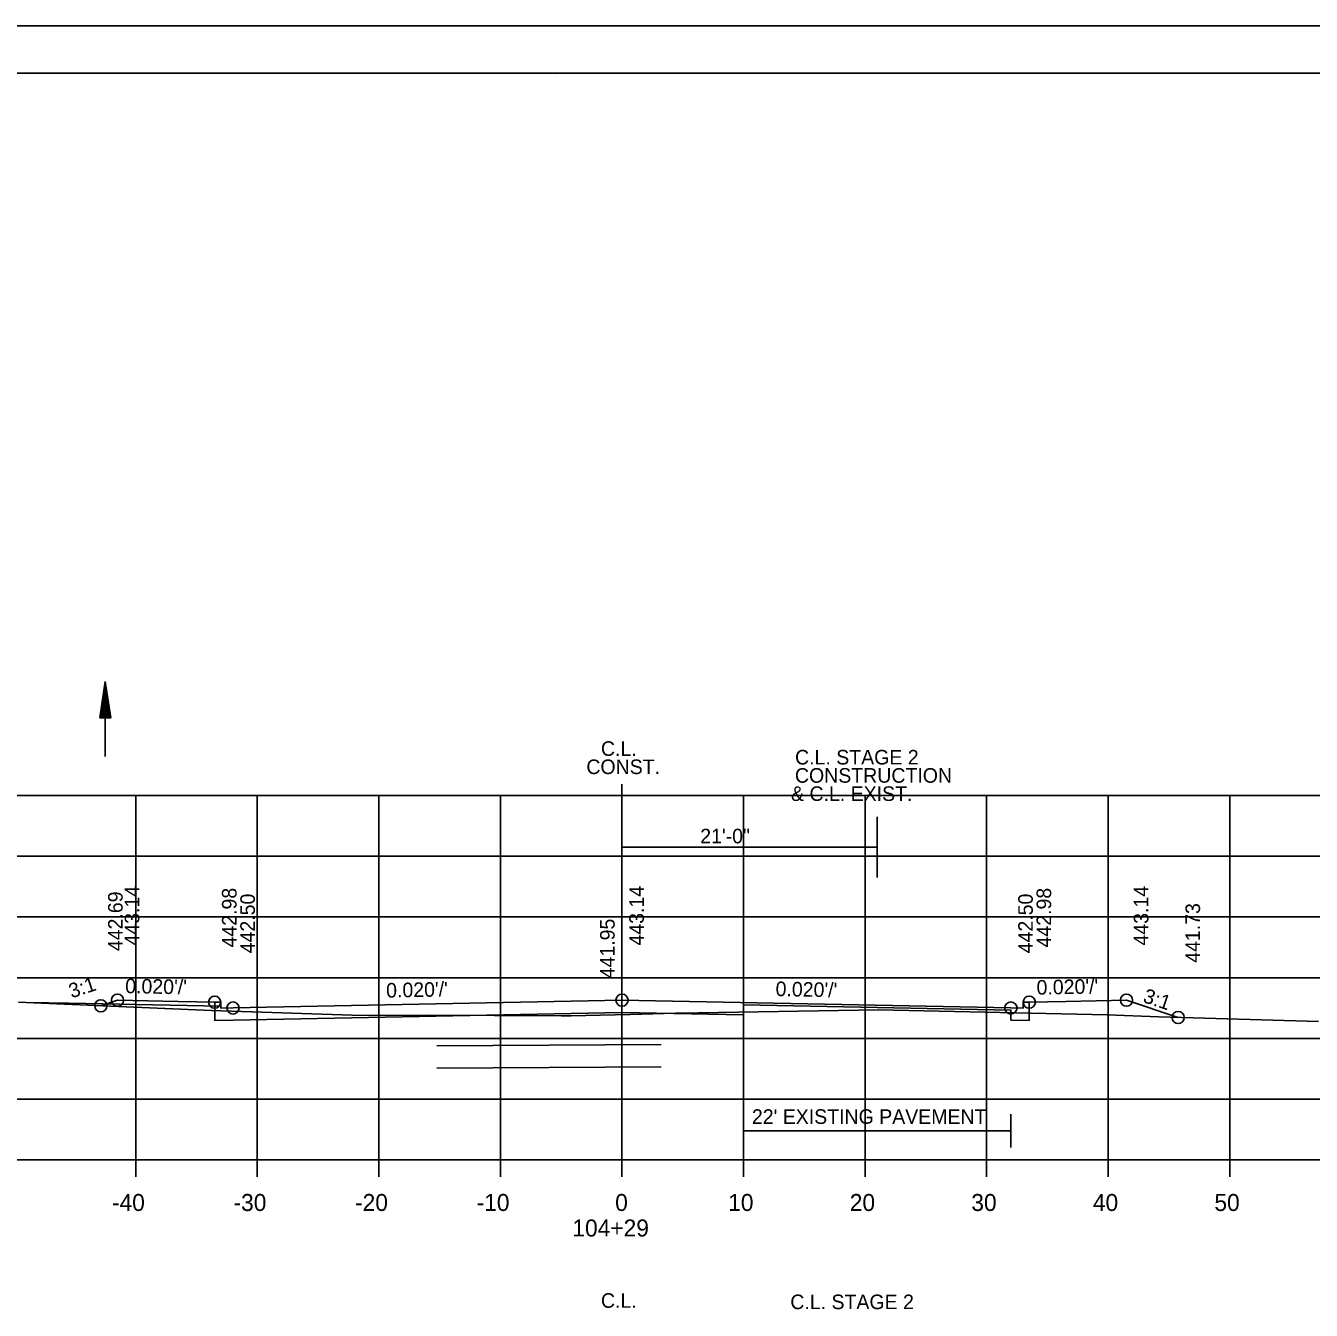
# Model space of a CAD drawing. Extents: x 1538688 to 1540766, y 656250 to 671912.
# Drawn here: x 1538809.1 to 1538914.9, y 657085.5 to 657191.2 of the extents above; entities that cross this region are included whole.
import ezdxf

# ---------------------------------------------------------------- set-up
doc = ezdxf.new("R2010")
doc.units = 0
for name, color, linetype in [('15', 7, 'Continuous'), ('16', 7, 'Continuous'), ('18', 7, 'Continuous'), ('20', 7, 'Continuous'), ('22', 7, 'Continuous'), ('26', 7, 'Continuous'), ('39', 7, 'Continuous'), ('41', 7, 'Continuous'), ('42', 7, 'Continuous'), ('7', 7, 'Continuous'), ('Borings', 7, 'Continuous'), ('Default', 7, 'Continuous'), ('Horizontal Alignment', 7, 'Continuous'), ('RipRap', 7, 'Continuous'), ('Wall Heights', 7, 'Continuous')]:
    doc.layers.add(name, color=color, linetype=linetype)

msp = doc.modelspace()

# ---------------------------------------------------------------- linework, layer by layer
at = {"layer": '15'}
for p, q in [((1538815.22, 657134.28), (1538815.67, 657137.28)), ((1538816.12, 657134.28), (1538815.67, 657137.28)), ((1538815.3, 657134.28), (1538815.67, 657136.78)), ((1538815.38, 657134.28), (1538815.67, 657136.26)), ((1538816.05, 657134.28), (1538815.67, 657136.78)), ((1538815.97, 657134.28), (1538815.67, 657136.26)), ((1538815.45, 657134.28), (1538815.67, 657135.76)), ((1538815.53, 657134.28), (1538815.67, 657135.25)), ((1538815.6, 657134.28), (1538815.67, 657134.75)), ((1538815.9, 657134.28), (1538815.67, 657135.76)), ((1538815.82, 657134.28), (1538815.67, 657135.25)), ((1538815.74, 657134.28), (1538815.67, 657134.75)), ((1538815.22, 657134.28), (1538816.12, 657134.28))]:
    msp.add_line(p, q, dxfattribs=at)
at = {"layer": '16'}
for p, q in [((1538809.4, 657110.85), (1538812.68, 657110.8)), ((1538812.68, 657110.8), (1538825.18, 657110.55))]:
    msp.add_line(p, q, dxfattribs=at)
at = {"layer": '18'}
msp.add_lwpolyline([(1538808.52, 657110.89), (1538817.4, 657110.49), (1538824.4, 657110.2), (1538836.81, 657109.79), (1538842.19, 657109.8), (1538853.2, 657109.75), (1538853.92, 657109.75), (1538853.99, 657109.75), (1538858.83, 657109.86), (1538858.85, 657109.86), (1538858.86, 657109.86), (1538862.58, 657109.97), (1538862.83, 657109.97), (1538879.29, 657110.26), (1538880.52, 657110.23), (1538898.09, 657109.84), (1538902.34, 657109.67), (1538915.48, 657109.29)], dxfattribs=at)
at = {"layer": '20'}
msp.add_lwpolyline([(1538815.3, 657110.58), (1538816.67, 657111.04), (1538821.67, 657110.94), (1538824.67, 657110.88), (1538825.17, 657110.88), (1538825.18, 657110.38), (1538826.18, 657110.4), (1538858.18, 657111.04), (1538890.18, 657110.4), (1538891.18, 657110.38), (1538891.19, 657110.88), (1538891.69, 657110.88), (1538894.69, 657110.94), (1538899.69, 657111.04), (1538903.94, 657109.62)], dxfattribs=at)
at = {"layer": '22'}
for p, q in [((1538718.18, 657127.89), (1538998.18, 657127.89)), ((1538818.18, 657097.89), (1538818.18, 657127.89)), ((1538828.18, 657097.89), (1538828.18, 657127.89)), ((1538838.18, 657097.89), (1538838.18, 657127.89)), ((1538848.18, 657097.89), (1538848.18, 657127.89)), ((1538858.18, 657097.89), (1538858.18, 657127.89)), ((1538868.18, 657097.89), (1538868.18, 657127.89)), ((1538878.18, 657097.89), (1538878.18, 657127.89)), ((1538888.18, 657097.89), (1538888.18, 657127.89)), ((1538898.18, 657097.89), (1538898.18, 657127.89)), ((1538908.18, 657097.89), (1538908.18, 657127.89)), ((1538718.18, 657122.89), (1538998.18, 657122.89)), ((1538718.18, 657117.89), (1538998.18, 657117.89)), ((1538718.18, 657112.89), (1538998.18, 657112.89)), ((1538718.18, 657107.89), (1538998.18, 657107.89)), ((1538718.18, 657102.89), (1538998.18, 657102.89)), ((1538718.18, 657097.89), (1538998.18, 657097.89))]:
    msp.add_line(p, q, dxfattribs=at)
at = {"layer": '26'}
for p, q in [((1538687.78, 657191.25), (1539021.11, 657191.25)), ((1538861.4, 657107.38), (1538842.96, 657107.27)), ((1538861.4, 657105.55), (1538842.96, 657105.44))]:
    msp.add_line(p, q, dxfattribs=at)
msp.add_lwpolyline([(1538687.77, 657191.25), (1539021.11, 657191.25), (1539021.11, 656977.91), (1538687.77, 656977.91)], close=True, dxfattribs=at)
for centre in [(1538816.67, 657111.04), (1538858.18, 657111.04), (1538899.69, 657111.04), (1538815.3, 657110.58), (1538824.67, 657110.88), (1538826.18, 657110.4), (1538826.18, 657110.4), (1538890.18, 657110.4), (1538890.18, 657110.4), (1538891.69, 657110.88), (1538903.94, 657109.62)]:
    msp.add_circle(centre, 0.5, dxfattribs=at)
at = {"layer": '39'}
msp.add_line((1538815.67, 657131.09), (1538815.67, 657137.28), dxfattribs=at)
at = {"layer": '7'}
for p, q in [((1538868.17, 657101.67), (1538868.17, 657098.92)), ((1538890.17, 657101.67), (1538890.17, 657098.92)), ((1538890.17, 657100.3), (1538868.17, 657100.3))]:
    msp.add_line(p, q, dxfattribs=at)
at = {"layer": 'Borings'}
for p, q in [((1538718.18, 657097.89), (1538998.18, 657097.89)), ((1538818.18, 657096.49), (1538818.18, 657097.89)), ((1538828.18, 657096.49), (1538828.18, 657097.89)), ((1538838.18, 657096.49), (1538838.18, 657097.89)), ((1538848.18, 657096.49), (1538848.18, 657097.89)), ((1538858.18, 657096.49), (1538858.18, 657097.89)), ((1538868.18, 657096.49), (1538868.18, 657097.89)), ((1538878.18, 657096.49), (1538878.18, 657097.89)), ((1538888.18, 657096.49), (1538888.18, 657097.89)), ((1538898.18, 657096.49), (1538898.18, 657097.89)), ((1538908.18, 657096.49), (1538908.18, 657097.89))]:
    msp.add_line(p, q, dxfattribs=at)
at = {"layer": 'Default'}
for p, q in [((1538858.18, 657128.81), (1538858.18, 657113.52)), ((1538879.17, 657126.13), (1538879.17, 657121.13)), ((1538879.17, 657123.63), (1538858.18, 657123.63))]:
    msp.add_line(p, q, dxfattribs=at)
at = {"layer": 'RipRap'}
for p, q in [((1538700.18, 657187.35), (1539016.36, 657187.35)), ((1538852.7, 657187.09), (1538852.7, 657187.09)), ((1538852.7, 657187.09), (1538852.7, 657187.09))]:
    msp.add_line(p, q, dxfattribs=at)
at = {"layer": 'Wall Heights'}
msp.add_lwpolyline([(1538891.69, 657110.88), (1538891.69, 657109.38), (1538890.18, 657109.4), (1538890.18, 657109.4), (1538890.18, 657110.23), (1538868.18, 657110.67), (1538868.18, 657109.84), (1538858.18, 657110.04), (1538826.18, 657109.4), (1538824.67, 657109.38), (1538824.67, 657110.88)], dxfattribs=at)

# ---------------------------------------------------------------- texts
at = {"layer": '41'}
for s, p in [('442.69', (1538817.1, 657115.08)), ('443.14', (1538818.47, 657115.54)), ('442.98', (1538826.47, 657115.38)), ('443.14', (1538859.98, 657115.54)), ('442.98', (1538893.49, 657115.38)), ('443.14', (1538901.49, 657115.54)), ('442.50', (1538827.98, 657114.9)), ('442.50', (1538891.98, 657114.9)), ('441.73', (1538905.74, 657114.12)), ('441.95', (1538857.58, 657112.84))]:
    msp.add_text(s, height=1.2, rotation=90, dxfattribs=at).set_placement(p)
at = {"layer": '42'}
for s, rotation, p in [('3:1', 18.4349, (1538812.9, 657111.18)), ("0.020'/'", 358.8542, (1538817.3, 657111.62)), ("0.020'/'", 1.1458, (1538838.79, 657111.25)), ("0.020'/'", 358.8542, (1538870.81, 657111.38)), ("0.020'/'", 1.1458, (1538892.3, 657111.49)), ('3:1', 341.5651, (1538900.97, 657110.9))]:
    msp.add_text(s, height=1.2, rotation=rotation, dxfattribs=at).set_placement(p)
at = {"layer": '7'}
msp.add_text("22' EXISTING PAVEMENT", height=1.2, dxfattribs=at).set_placement((1538868.87, 657100.86))
at = {"layer": 'Default'}
for s, p in [('C.L.', (1538856.45, 657131.15)), ('C.L. STAGE 2', (1538872.42, 657130.44)), ('CONST.', (1538855.25, 657129.65)), ('CONSTRUCTION', (1538872.41, 657128.94)), ('& C.L. EXIST.', (1538872.09, 657127.44)), ('21\'-0"', (1538864.62, 657123.95)), ('C.L.', (1538856.45, 657085.72)), ('C.L. STAGE 2', (1538872.03, 657085.61))]:
    msp.add_text(s, height=1.2, dxfattribs=at).set_placement(p)
at = {"layer": 'Horizontal Alignment'}
for s, p in [('-40', (1538816.22, 657093.69)), ('-30', (1538826.22, 657093.69)), ('-20', (1538836.22, 657093.69)), ('-10', (1538846.22, 657093.69)), ('0', (1538857.62, 657093.69)), ('10', (1538866.92, 657093.69)), ('20', (1538876.92, 657093.69)), ('30', (1538886.92, 657093.69)), ('40', (1538896.92, 657093.69)), ('50', (1538906.92, 657093.69)), ('104+29', (1538854.1, 657091.59))]:
    msp.add_text(s, height=1.4, dxfattribs=at).set_placement(p)

doc.saveas('drawing.dxf')
